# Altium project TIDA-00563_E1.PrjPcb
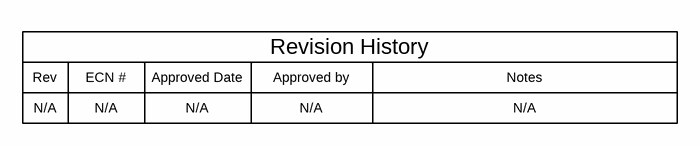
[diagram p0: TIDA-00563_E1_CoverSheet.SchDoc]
CopyrightYear: 2015; EVM_Orderable: N/A; PCB_Layout: SY; PCB_Rev: E1; PRJ_Customer: Public Release; PRJ_Engineer: FA&C; PRJ_Number: TIDA-00563; PRJ_Title: Inductive Proximity Switch BoosterPack; SCH_Rev: E1; TechSupport: http://www.ti.com/support; TID: TIDA-00563
3 sheets, 82 parts. Net scope: global (net labels, ports and power ports of the same name join across sheets).
Board file: TIDA-00563_E1.PcbDoc
Sheets:
  TIDA-00563_E1_CoverSheet.SchDoc
  TIDA-00563_E1_Hardware.SchDoc
  TIDA-00563_E1_LDC1101_BoosterPack.SchDoc

## Sheet TIDA-00563_E1_CoverSheet.SchDoc: Block Diagram
size 431 x 279 mm; Date: Not shown in title block; ApprovedBy: Not shown in title block; CheckedBy: Not shown in title block; Author: Not shown in title block; CompanyName: Not shown in title block; DrawnBy: SY; Engineer: Not shown in title block; Organization: Not shown in title block; Address1: Not shown in title block; Address2: Not shown in title block; Address3: Not shown in title block; Address4: Not shown in title block; DocumentNumber: 1; Revision: Use project parameter SCH_Rev; SheetNumber: 1; SheetTotal: 3; PageSetup: Record=PageOptions¦CenterHorizontal=True¦CenterVertical=True¦PrintScale=1.00¦XCorrection=1.00¦YCorrection=1.00¦PrintKind=0¦BorderSize=5000000¦LeftOffset=0¦BottomOffset=0¦Orientation=2¦PaperLength=1000¦PaperWidth=1000¦Scale=100¦PaperSource=15¦PrintQuality=600¦MediaType=1¦DitherType=10¦PaperKind=Letter¦PrintScaleMode=1

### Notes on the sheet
- Rev
- N/A
- ECN #
- Approved Date
- Approved by
- Revision History
- Notes

## Sheet TIDA-00563_E1_Hardware.SchDoc: Hardware
size 431 x 279 mm; Date: Not shown in title block; ApprovedBy: Not shown in title block; CheckedBy: Not shown in title block; Author: Not shown in title block; CompanyName: Not shown in title block; DrawnBy: SY; Engineer: Not shown in title block; Organization: Not shown in title block; Address1: Not shown in title block; Address2: Not shown in title block; Address3: Not shown in title block; Address4: Not shown in title block; DocumentNumber: 1; Revision: Use project parameter SCH_Rev; SheetNumber: 3; SheetTotal: 3; PageSetup: Record=PageOptions¦CenterHorizontal=True¦CenterVertical=True¦PrintScale=1.00¦XCorrection=1.00¦YCorrection=1.00¦PrintKind=0¦BorderSize=5000000¦LeftOffset=0¦BottomOffset=0¦Orientation=2¦PaperLength=1000¦PaperWidth=1000¦Scale=100¦PaperSource=15¦PrintQuality=600¦MediaType=1¦DitherType=10¦PaperKind=Letter¦PrintScaleMode=1
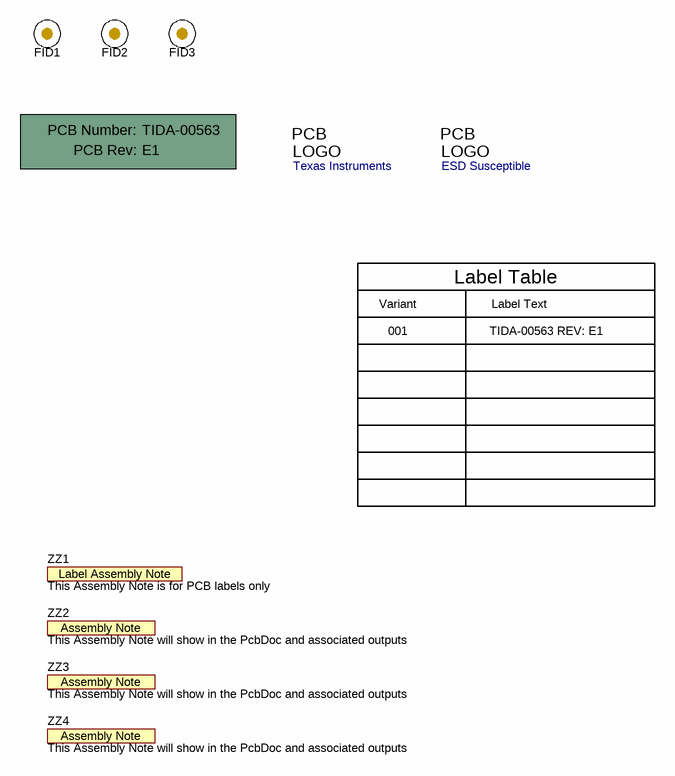
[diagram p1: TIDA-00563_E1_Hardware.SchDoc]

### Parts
!PCB1  Printed Circuit Board  (value not drawn)  (mechanical)
FID1  Fiducial  [Fiducial10-20]  (value not drawn)
FID2  Fiducial  [Fiducial10-20]  (value not drawn)
FID3  Fiducial  [Fiducial10-20]  (value not drawn)
Logo1  Texas Instruments  [TI_Stacked_Overlay_Medium_Vertical]  (no BOM)
Logo2  ESD Susceptible  [ESD_Overlay_Large]  (no BOM)
ZZ1  This Assembly Note is for PCB labels only  [AssemblyNoteLabel]  (no BOM)
ZZ2  This Assembly Note will show in the PcbDoc and associated outputs  [AssemblyNote]  (no BOM)
ZZ3  This Assembly Note will show in the PcbDoc and associated outputs  [AssemblyNote]  (no BOM)
ZZ4  This Assembly Note will show in the PcbDoc and associated outputs  [AssemblyNote]  (no BOM)

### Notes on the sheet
- Label Table
- Variant
- 001
- Label Text
- TIDA-00563 REV: E1

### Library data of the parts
!PCB1 = PCB: Manufacturer: Any; PartNumber: TIDA-00563; SymbolCreator: a0412235
FID1-FID3 = Fiducial: Fiducial mark.  There is nothing to buy or mount.; SymbolCreator: codlsc
Logo1 = TI_Logo: Texas Instrument Corporate Signature; SymbolCreator: a0412235
Logo2 = ESD_Susceptible: ESD Susceptible Symbol; SymbolCreator: a0412235
ZZ1 = AssemblyNoteLabel: SymbolCreator: a0412235
ZZ2-ZZ4 = AssemblyNote: SymbolCreator: codlsc

## Sheet TIDA-00563_E1_LDC1101_BoosterPack.SchDoc: MSP430 MCU & LDC1101 Interface Circuitry
size 431 x 279 mm; Date: Not shown in title block; ApprovedBy: Not shown in title block; CheckedBy: Not shown in title block; Author: Not shown in title block; CompanyName: Not shown in title block; DrawnBy: SY; Engineer: Not shown in title block; Organization: Not shown in title block; Address1: Not shown in title block; Address2: Not shown in title block; Address3: Not shown in title block; Address4: Not shown in title block; DocumentNumber: 1; Revision: Use project parameter SCH_Rev; SheetNumber: 2; SheetTotal: 3; PageSetup: Record=PageOptions¦CenterHorizontal=True¦CenterVertical=True¦PrintScale=1.00¦XCorrection=1.00¦YCorrection=1.00¦PrintKind=0¦BorderSize=5000000¦LeftOffset=0¦BottomOffset=0¦Orientation=2¦PaperLength=1000¦PaperWidth=1000¦Scale=100¦PaperSource=15¦PrintQuality=600¦MediaType=1¦DitherType=10¦PaperKind=Letter¦PrintScaleMode=1
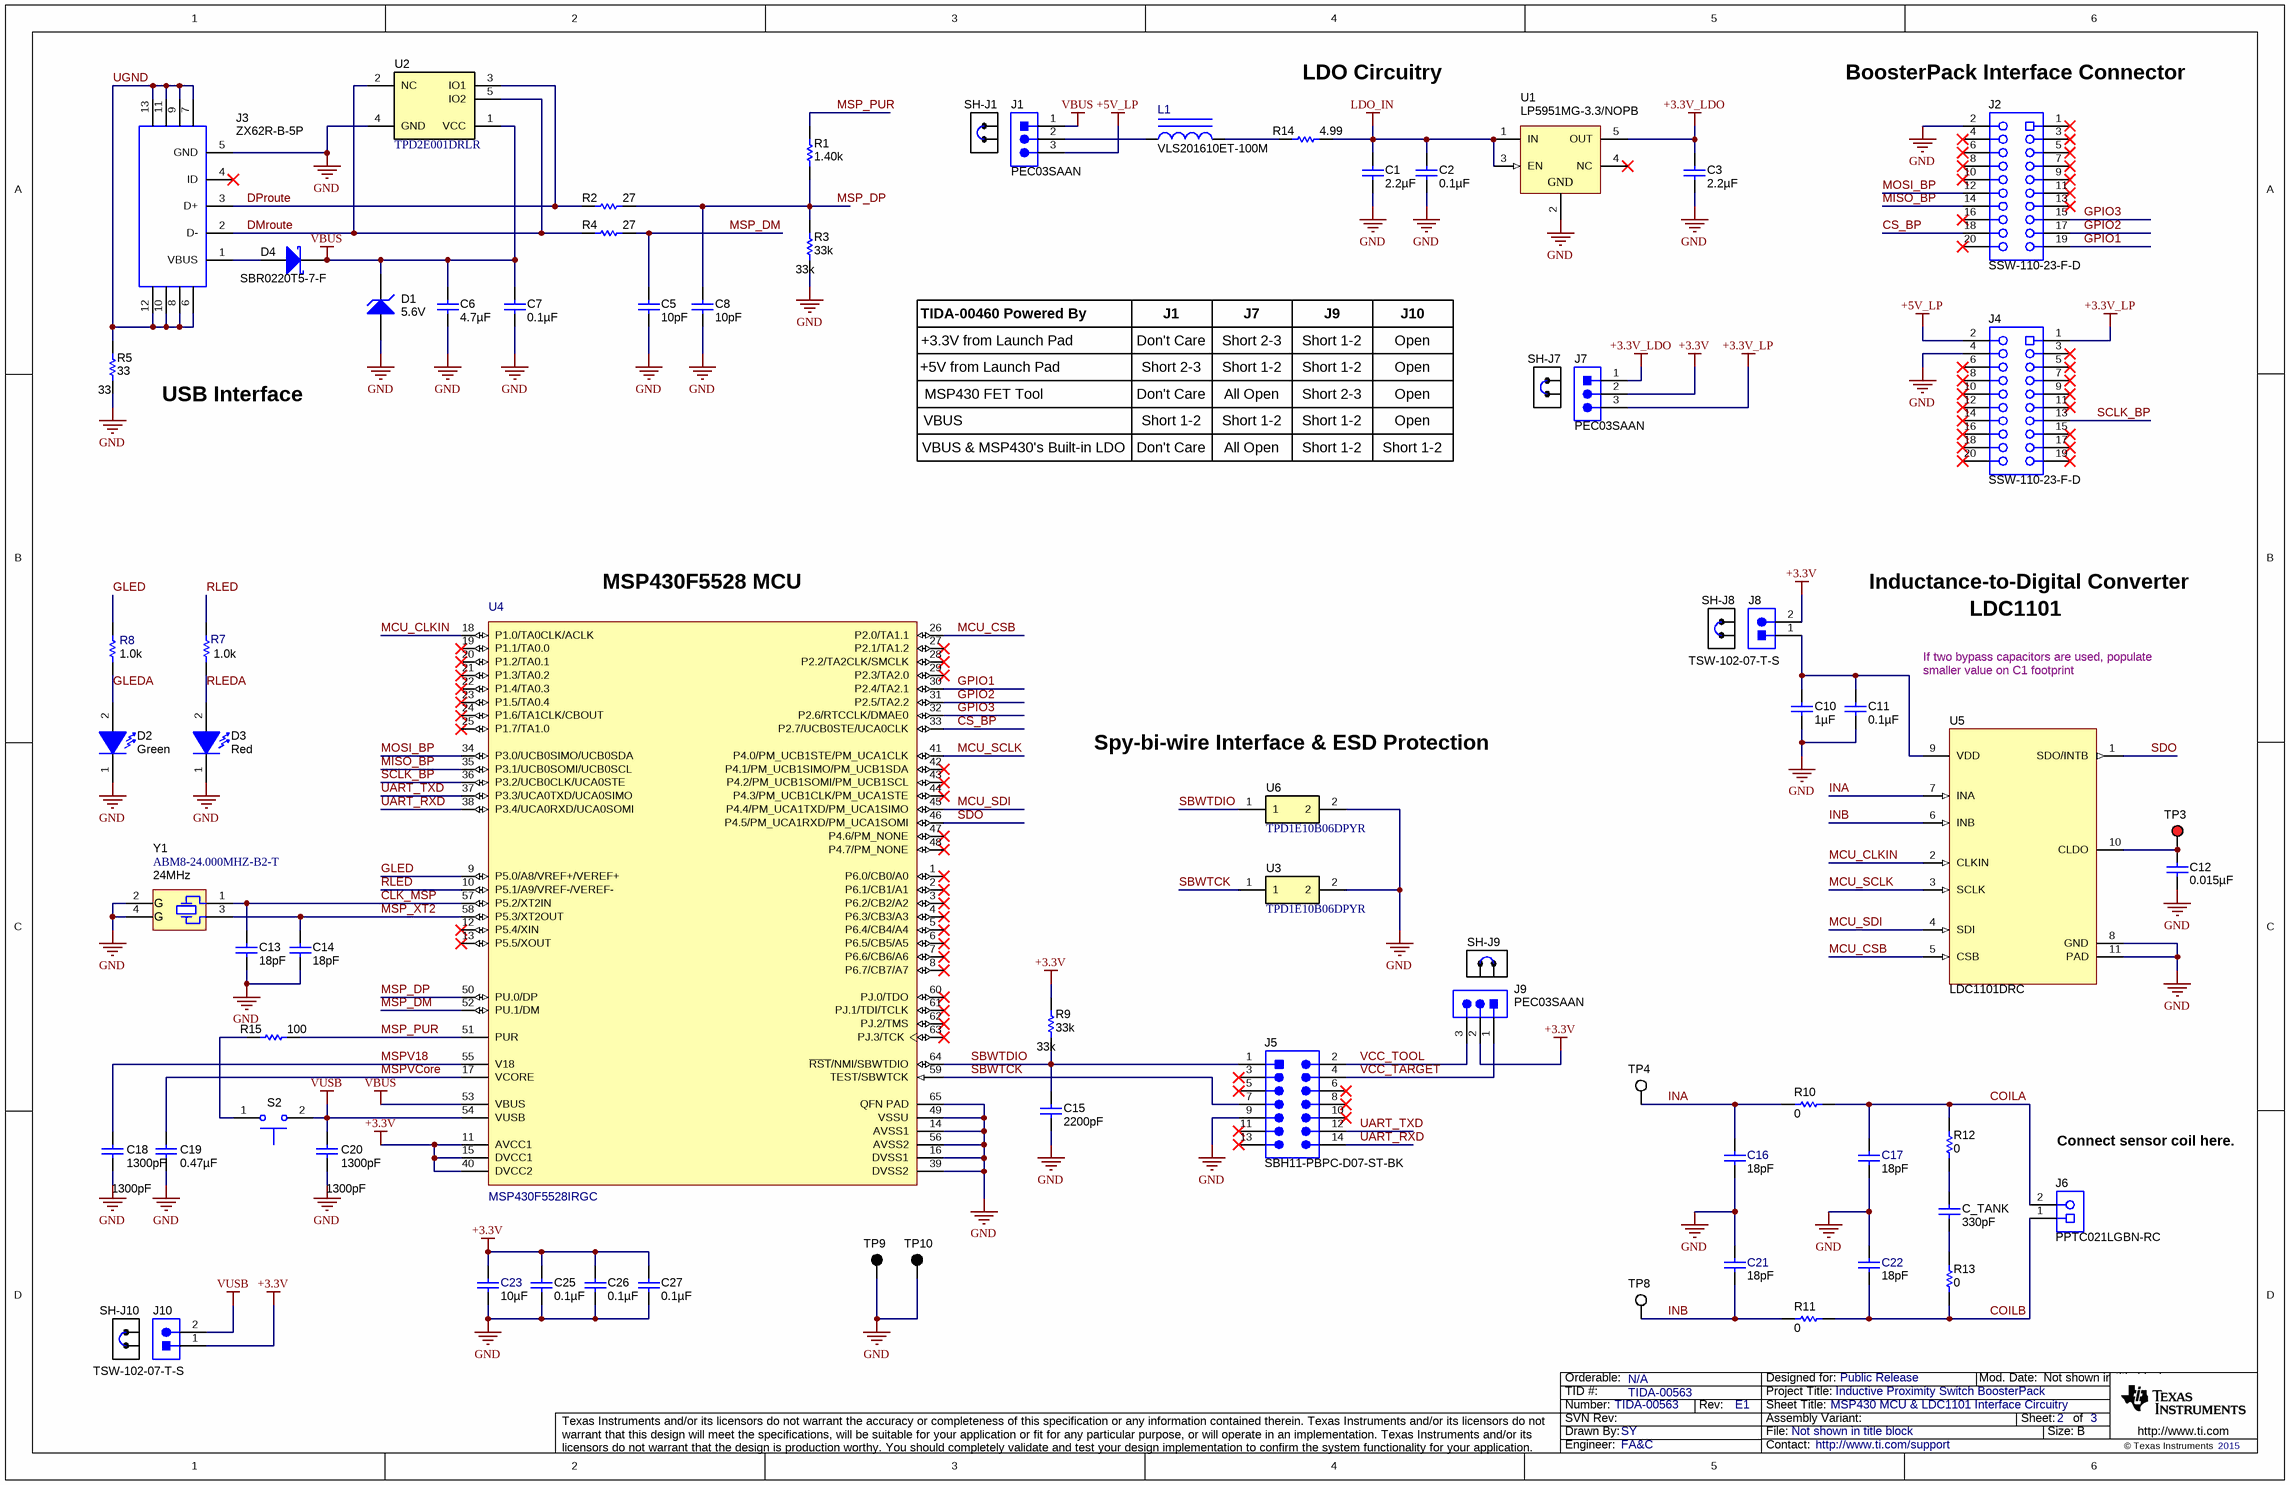
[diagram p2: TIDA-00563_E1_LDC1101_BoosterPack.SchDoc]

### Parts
C1  ValueDisplayed: 2.2µF  [0603]  (hidden comment: C0603C225K8PACTU)
C2  ValueDisplayed: 0.1µF  [0402]  (hidden comment: C1005X7R1H104K050BB)
C3  ValueDisplayed: 2.2µF  [0603]  (hidden comment: C0603C225K8PACTU)
C5  ValueDisplayed: 10pF  [0402]  (hidden comment: 500R07S100JV4T)
C6  ValueDisplayed: 4.7µF  [0805]  (hidden comment: GRM21BR71C475KA73L)
C7  ValueDisplayed: 0.1µF  [0402]  (hidden comment: C1005X7R1H104K050BB)
C8  ValueDisplayed: 10pF  [0402]  (hidden comment: 500R07S100JV4T)
C10  ValueDisplayed: 1µF  [0402]  (hidden comment: GRM155R61A105KE15D)
C11  ValueDisplayed: 0.1µF  [0402]  (hidden comment: C1005X7R1H104K050BB)
C12  ValueDisplayed: 0.015µF  [0603]  (hidden comment: GRM188R71C153KA01D)
C13  ValueDisplayed: 18pF  [0402]  (hidden comment: GRM1555C1H180JA01D)
C14  ValueDisplayed: 18pF  [0402]  (hidden comment: GRM1555C1H180JA01D)
C15  ValueDisplayed: 2200pF  [0402]  (hidden comment: GRM155R70J222KA01D)
C16  ValueDisplayed: 18pF  [0603]  (hidden comment: GRM1885C2A180JA01D)
C17  ValueDisplayed: 18pF  [0603]  (hidden comment: GRM1885C2A180JA01D)
C18  value 1300pF  [0402]  (hidden comment: 0402YC132KAT2A)
C19  ValueDisplayed: 0.47µF  [0603]  (hidden comment: C0603C474K8RACTU)
C20  value 1300pF  [0402]  (hidden comment: 0402YC132KAT2A)
C21  ValueDisplayed: 18pF  [0603]  (hidden comment: GRM1885C2A180JA01D)
C22  ValueDisplayed: 18pF  [0603]  (hidden comment: GRM1885C2A180JA01D)
C23  ValueDisplayed: 10µF  [0603]  (hidden comment: C1608X5R1A106M)
C25  ValueDisplayed: 0.1µF  [0402]  (hidden comment: C1005X7R1H104K050BB)
C26  ValueDisplayed: 0.1µF  [0402]  (hidden comment: C1005X7R1H104K050BB)
C27  ValueDisplayed: 0.1µF  [0402]  (hidden comment: C1005X7R1H104K050BB)
C_TANK  ValueDisplayed: 330pF  [0603]  (hidden comment: C1608C0G1H331F080AA)
D1  value 5.6V  [SOD-123]  (hidden comment: MMSZ5232B-7-F)
D2  value Green  [WL-SMCW_GREEN]  (hidden comment: 150060GS75000)
D3  value Red  [WL-SMCW_RED]  (hidden comment: 150060RS75000)
D4  SBR0220T5-7-F  [SOD-523]
J1  PEC03SAAN  [CONN_PEC03SAAN]
J2  SSW-110-23-F-D  [CONN_SSW-110-23-F-D]
J3  ZX62R-B-5P  [Hirose_ZX62R-B-5P]
J4  SSW-110-23-F-D  [CONN_SSW-110-23-F-D]
J5  SBH11-PBPC-D07-ST-BK  [CONN_SBH11-PBPC-D07-ST-BK]
J6  PPTC021LGBN-RC  [Sullins_xPxC021LGBN]
J7  PEC03SAAN  [CONN_PEC03SAAN]
J8  TSW-102-07-T-S  [Samtec_TSW-102-07-T-S]
J9  PEC03SAAN  [CONN_PEC03SAAN]
J10  TSW-102-07-T-S  [Samtec_TSW-102-07-T-S]
L1  VLS201610ET-100M  [VLS201610ET]
R1  ValueDisplayed: 1.40k  [0402]  (hidden comment: ERJ-2RKF1401X)
R2  ValueDisplayed: 27  [0402]  (hidden comment: CRCW040227R0JNED)
R3  value 33k  [0402]  (hidden comment: CRCW040233K0JNED)
R4  ValueDisplayed: 27  [0402]  (hidden comment: CRCW040227R0JNED)
R5  value 33  [0603]  (hidden comment: CRCW060333R0JNEA)
R7  value 1.0k  [0402]  (hidden comment: CRCW04021K00JNED)
R8  value 1.0k  [0402]  (hidden comment: CRCW04021K00JNED)
R9  value 33k  [0402]  (hidden comment: CRCW040233K0JNED)
R10  ValueDisplayed: 0  [0603]  (hidden comment: ERJ-3GEY0R00V)
R11  ValueDisplayed: 0  [0603]  (hidden comment: ERJ-3GEY0R00V)
R12  ValueDisplayed: 0  [0402]  (hidden comment: CRCW04020000Z0ED)
R13  ValueDisplayed: 0  [0402]  (hidden comment: CRCW04020000Z0ED)
R14  ValueDisplayed: 4.99  [0603]  (hidden comment: RC0603FR-074R99L)
R15  ValueDisplayed: 100  [0402]  (hidden comment: ERJ-2RKF1000X)
S2  SKRKAEE010  [SW_SKRKAEE010]  (value not drawn)
SH-J1  969102-0000-DA  [SNT-100-BK-G]  (value not drawn)
SH-J7  969102-0000-DA  [SNT-100-BK-G]  (value not drawn)
SH-J8  969102-0000-DA  [SNT-100-BK-G]  (value not drawn)
SH-J9  969102-0000-DA  [SNT-100-BK-G]  (value not drawn)
SH-J10  969102-0000-DA  [SNT-100-BK-G]  (value not drawn)
TP3  5000  [Keystone5000]  (value not drawn)
TP4  5002  [Keystone5002]  (value not drawn)
TP8  5002  [Keystone5002]  (value not drawn)
TP9  5001  [Keystone5001]  (value not drawn)
TP10  5001  [Keystone5001]  (value not drawn)
U1  LP5951MG-3.3/NOPB  [MAA05A_N]
U2  TPD2E001DRLR  [DRL0005A]
U3  TPD1E10B06DPYR  [DPY0002A]
U4  MSP430F5528IRGC  [RGC0064B]
U5  LDC1101DRC  [DRC0010J]
U6  TPD1E10B06DPYR  [DPY0002A]
Y1  ABM8-24.000MHZ-B2-T  Frequency: 24MHz  [XTAL_ABM8]

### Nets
+3.3V: C23.1 C25.1 C26.1 C27.1 J7.2 J8.2 J9.2 J10.1 R9.1 U4.11(AVCC1) U4.15(DVCC1) U4.40(DVCC2)
+3.3V_LDO: C3.1 J7.1 U1.5(OUT)
+3.3V_LP: J4.1 J7.3
+5V_LP: J1.3 J4.2
GND: C1.2 C2.2 C3.2 C5.2 C6.2 C7.2 C8.2 C10.2 C11.2 C12.2 C13.2 C14.2 C15.2 C16.1 C17.1 C18.2 C19.2 C20.2 C21.2 C22.2 C23.2 C25.2 C26.2 C27.2 D1.2(A) D2.1(K) D3.1(K) J2.2 J3.5(GND) J4.4 J5.9 R3.1 R5.1 TP9.1 TP10.1 U1.2(GND) U2.4(GND) U3.2 U4.14(AVSS1) U4.16(DVSS1) U4.39(DVSS2) U4.49(VSSU) U4.56(AVSS2) U4.65(QFN_PAD) U5.8(GND) U5.11(PAD) U6.2 Y1.2(GND) Y1.4(GND)
LDO_IN: C1.1 C2.1 R14.2 U1.1(IN) U1.3(EN)
VBUS: C6.1 C7.1 D1.1(K) D4.1(K) J1.1 U2.1(VCC) U4.53(VBUS)
VUSB: C20.1 J10.2 S2.2 U4.54(VUSB)
CLK_MSP: C13.1 U4.57(P5.2/XT2IN) Y1.1
COILA: C17.2 J6.2 R10.2 R12.2
COILB: C22.1 J6.1 R11.2 R13.1
CS_BP: J2.18 U4.33(P2.7/UCB0STE/UCA0CLK)
DMroute: J3.2(D-) R4.1 U2.2(NC) U2.5(IO2)
DProute: J3.3(D+) R2.1 U2.3(IO1)
GLED: R8.1 U4.9(P5.0/A8/VREF+/VEREF+)
GLEDA: D2.2(A) R8.2
GPIO1: J2.19 U4.30(P2.4/TA2.1)
GPIO2: J2.17 U4.31(P2.5/TA2.2)
GPIO3: J2.15 U4.32(P2.6/RTCCLK/DMAE0)
INA: C16.2 R10.1 TP4.1 U5.7(INA)
INB: C21.1 R11.1 TP8.1 U5.6(INB)
MCU_CLKIN: U4.18(P1.0/TA0CLK/ACLK) U5.2(CLKIN)
MCU_CSB: U4.26(P2.0/TA1.1) U5.5(CSB)
MCU_SCLK: U4.41(P4.0/PM_UCB1STE/PM_UCA1CLK) U5.3(SCLK)
MCU_SDI: U4.45(P4.4/PM_UCA1TXD/PM_UCA1SIMO) U5.4(SDI)
MISO_BP: J2.14 U4.35(P3.1/UCB0SOMI/UCB0SCL)
MOSI_BP: J2.12 U4.34(P3.0/UCB0SIMO/UCB0SDA)
MSP_DM: C5.1 R4.2 U4.52(PU.1/DM)
MSP_DP: C8.1 R1.1 R2.2 R3.2 U4.50(PU.0/DP)
MSP_PUR: R1.2 R15.1 U4.51(PUR)
MSP_XT2: C14.1 U4.58(P5.3/XT2OUT) Y1.3
MSPV18: C18.1 U4.55(V18)
MSPVCore: C19.1 U4.17(VCORE)
RLED: R7.1 U4.10(P5.1/A9/VREF-/VEREF-)
RLEDA: D3.2(A) R7.2
SBWTCK: J5.7 U3.1 U4.59(TEST/SBWTCK)
SBWTDIO: C15.1 J5.1 R9.2 U4.64(~{RST}/NMI/SBWTDIO) U6.1
SCLK_BP: J4.13 U4.36(P3.2/UCB0CLK/UCA0STE)
SDO: U4.46(P4.5/PM_UCA1RXD/PM_UCA1SOMI) U5.1(SDO/INTB)
UART_RXD: J5.14 U4.38(P3.4/UCA0RXD/UCA0SOMI)
UART_TXD: J5.12 U4.37(P3.3/UCA0TXD/UCA0SIMO)
UGND: J3.6 J3.7 J3.8 J3.9 J3.10 J3.11 J3.12 J3.13 R5.2
VCC_TARGET: J5.4 J9.1
VCC_TOOL: J5.2 J9.3
NetC10_1: C10.1 C11.1 J8.1 U5.9(VDD)
NetC12_1: C12.1 TP3.1 U5.10(CLDO)
NetC_TANK_1: C_TANK.1 R12.1
NetC_TANK_2: C_TANK.2 R13.2
NetD4_2: D4.2(A) J3.1(VBUS)
NetJ1_2: J1.2 L1.1
NetL1_2: L1.2 R14.1
NetR15_2: R15.2 S2.1

Not connected (* = marked no-connect by the designer): J2 1* 3* 4* 5* 6* 7* 8* 9* 10* 11* 13* 16* 20*; J3 4(ID)*; J4 3* 5* 6* 7* 8* 9* 10* 11* 12* 14* 15* 16* 17* 18* 19* 20*; J5 3* 5* 6* 8* 10* 11* 13*; U1 4(NC)*; U4 1(P6.0/CB0/A0)* 2(P6.1/CB1/A1)* 3(P6.2/CB2/A2)* 4(P6.3/CB3/A3)* 5(P6.4/CB4/A4)* 6(P6.5/CB5/A5)* 7(P6.6/CB6/A6)* 8(P6.7/CB7/A7)* 12(P5.4/XIN)* 13(P5.5/XOUT)* 19(P1.1/TA0.0)* 20(P1.2/TA0.1)* 21(P1.3/TA0.2)* 22(P1.4/TA0.3)* 23(P1.5/TA0.4)* 24(P1.6/TA1CLK/CBOUT)* 25(P1.7/TA1.0)* 27(P2.1/TA1.2)* 28(P2.2/TA2CLK/SMCLK)* 29(P2.3/TA2.0)* 42(P4.1/PM_UCB1SIMO/PM_UCB1SDA)* 43(P4.2/PM_UCB1SOMI/PM_UCB1SCL)* 44(P4.3/PM_UCB1CLK/PM_UCA1STE)* 47(P4.6/PM_NONE)* 48(P4.7/PM_NONE)* 60(PJ.0/TDO)* 61(PJ.1/TDI/TCLK)* 62(PJ.2/TMS)* 63(PJ.3/TCK)*

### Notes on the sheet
- LDO Circuitry
- (near J2) BoosterPack Interface Connector
- +5V from Launch Pad
- +3.3V from Launch Pad
- TIDA-00460 Powered By
- J1
- Don't Care
- Short 2-3
- J7
- Short 1-2
- J9
- J10
- Open
- (near R5) USB Interface
- VBUS
- MSP430 FET Tool
- All Open
- VBUS & MSP430's Built-in LDO
- (near U4) MSP430F5528 MCU
- LDC1101
- Inductance-to-Digital Converter
- If two bypass capacitors are used, populate smaller value on C1 footprint
- Spy-bi-wire Interface & ESD Protection
- (near J6) Connect sensor coil here.

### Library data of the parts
C1 C3 = C0603C225K8PACTU: CAP, CERM, 2.2 µF, 10 V, +/- 10%, X5R, 0603; Manufacturer: Kemet; Polarized: N; CompType: Capacitor; Value: 2.2uF; U/M: EA; Cap_F: 0.0000022; Tolerance_%: 10; Value1: Unknown; Value2: 10V; TaMin_C: -55; TaMax_C: 85; AEC Category: Q200
C2 C7 C11 C25-C27 = C1005X7R1H104K050BB: CAP, CERM, 0.1 µF, 50 V, +/- 10%, X7R, 0402; Manufacturer: TDK; Polarized: N; CompType: Capacitor; Value: 0.1uF; U/M: EA; Cap_F: 0.0000001; Tolerance_%: 10; Value1: Unknown; VDC_V: 50; Value2: 50V; TaMin_C: -55; TaMax_C: 125; AEC Category: Q200
C5 C8 = 500R07S100JV4T: CAP, CERM, 10 pF, 50 V, +/- 5%, C0G/NP0, 0402; Manufacturer: Johanson Technology; Polarized: N; CompType: Capacitor; Value: 10pF; U/M: EA; Cap_F: 0.00000000001; Tolerance_%: 5; Value1: Unknown; VDC_V: 50; Value2: 50V; TaMin_C: -55; TaMax_C: 125; AEC Category: Q200
C6 = GRM21BR71C475KA73L: CAP, CERM, 4.7 µF, 16 V, +/- 10%, X7R, 0805; Manufacturer: MuRata; Polarized: N; CompType: Capacitor; Value: 4.7uF; U/M: EA; Cap_F: 0.0000047; Tolerance_%: 10; ESR_ohm: 0.006; Value1: 0.006 ohm; VDC_V: 16; Value2: 16V; TaMin_C: -55; TaMax_C: 125; AEC Category: Q200
C10 = GRM155R61A105KE15D: CAP, CERM, 1 µF, 10 V, +/- 10%, X5R, 0402; Manufacturer: MuRata; Polarized: N; CompType: Capacitor; Value: 1uF; U/M: EA; Cap_F: 0.000001; Tolerance_%: 10; Value1: Unknown; Value2: 10V; TaMin_C: -55; TaMax_C: 85; AEC Category: Q200
C12 = GRM188R71C153KA01D: CAP, CERM, 0.015 µF, 16 V, +/- 10%, X7R, 0603; Manufacturer: MuRata; Polarized: N; CompType: Capacitor; Value: 0.015uF; U/M: EA; Cap_F: 0.000000015; Tolerance_%: 10; Value1: Unknown; VDC_V: 16; Value2: 16V; TaMin_C: -55; TaMax_C: 125; AEC Category: Q200
C13 C14 = GRM1555C1H180JA01D: CAP, CERM, 18 pF, 50 V, +/- 5%, C0G/NP0, 0402; Manufacturer: MuRata; Polarized: N; CompType: Capacitor; Value: 18pF; U/M: EA; Cap_F: 0.000000000018; Tolerance_%: 5; Value1: Unknown; VDC_V: 50; Value2: 50V; TaMin_C: -55; TaMax_C: 125; AEC Category: Q200
C15 = GRM155R70J222KA01D: CAP, CERM, 2200 pF, 6.3 V, +/- 10%, X7R, 0402; Manufacturer: MuRata; Polarized: N; CompType: Capacitor; Value: 2200pF; U/M: EA; Cap_F: 0.0000000022; Tolerance_%: 10; Value1: Unknown; VDC_V: 6.3; Value2: 6.3V; TaMin_C: -55; TaMax_C: 125; AEC Category: Q200
C16 C17 C21 C22 = GRM1885C2A180JA01D: CAP, CERM, 18 pF, 100 V, +/- 5%, C0G/NP0, 0603; Manufacturer: MuRata; Polarized: N; CompType: Capacitor; Value: 18pF; U/M: EA; Cap_F: 0.000000000018; Tolerance_%: 5; Value1: Unknown; VDC_V: 100; Value2: 100V; TaMin_C: -55; TaMax_C: 125; AEC Category: Q200
C18 C20 = 0402YC132KAT2A: CAP, CERM, 1300 pF, 16 V, +/- 10%, X7R, 0402; Manufacturer: AVX; Polarized: N; CompType: Capacitor; U/M: EA; Cap_F: 0.0000000013; Tolerance_%: 10; VDC_V: 16; TaMin_C: -55; TaMax_C: 125; Value1: Unknown; Value2: 16V; AEC Category: Q200
C19 = C0603C474K8RACTU: CAP, CERM, 0.47 µF, 10 V, +/- 10%, X7R, 0603; Manufacturer: Kemet; Polarized: N; CompType: Capacitor; Value: 0.47uF; U/M: EA; Cap_F: 0.00000047; Tolerance_%: 10; Value1: Unknown; Value2: 10V; TaMin_C: -55; TaMax_C: 125; AEC Category: Q200
C23 = C1608X5R1A106M: CAP, CERM, 10 µF, 10 V, +/- 20%, X5R, 0603; Manufacturer: TDK; Polarized: N; CompType: Capacitor; Value: 10uF; U/M: EA; Cap_F: 0.00001; Tolerance_%: 20; ESR_ohm: 0.0078; Value1: 0.0078 ohm; VDC_V: 10; Value2: 10V; IRMS_A: 1.85; TaMin_C: -55; TaMax_C: 85; AEC Category: Q200
C_TANK = C1608C0G1H331F080AA: CAP, CERM, 330 pF, 50 V, +/- 1%, C0G/NP0, 0603; Manufacturer: TDK; Polarized: N; CompType: Capacitor; Value: 330pF; U/M: EA; Cap_F: 0.00000000033; Tolerance_%: 1; Value1: Unknown; VDC_V: 50; Value2: 50V; TaMin_C: -55; TaMax_C: 125; AEC Category: Q200
D1 = MMSZ5232B-7-F: Diode, Zener, 5.6 V, 500 mW, SOD-123; Manufacturer: Diodes Inc.; U/M: EA; Power_W: 0.5; Vz_V: 5.6; Value1: 0.5W; RJA_CperW: 350; SymbolCreator: a0412235; AEC Category: Q101
D2 = 150060GS75000: LED, Green, SMD; Manufacturer: Wurth Elektronik; Type: InGaN; Vf_V: 3.2; Value2: 3.2V; Io_A: 0.02; Tjmax_C: 85; Value1: W; Angle: 140; U/M: EA
D3 = 150060RS75000: LED, Red, SMD; Manufacturer: Wurth Elektronik; Type: AlInGaP; Vf_V: 2; Value2: 2V; Io_A: 0.03; Vr_V: 5; Tjmax_C: 85; Power_TotalModule: 0.072; Value1: 0.072W; Angle: 140; U/M: EA
D4 = SBR0220T5-7-F: Diode, Schottky, 20 V, 0.2 A, SOD-523; Manufacturer: Diodes Inc.; U/M: EA; Vf_V: 0.47; Value: 20V; Value1: 0.2A; Value2: 0.47V; Io_A: 0.2; Vr_V: 20; AEC Category: Q101
J1 J7 J9 = PEC03SAAN: Header, 100mil, 3x1, Tin plated, TH; Manufacturer: Sullins Connector Solutions; SymbolCreator: a0799628; U/M: EA
J2 J4 = SSW-110-23-F-D: Connector, Receptacle, 100mil, 10x2, Gold plated, TH; Manufacturer: Samtec; SymbolCreator: a0412235; U/M: EA
J3 = ZX62R-B-5P: Connector, Receptacle, Micro-USB Type B, SMT; Manufacturer: Hirose Electric Co. Ltd.; SymbolCreator: a0799628; U/M: EA
J5 = SBH11-PBPC-D07-ST-BK: Header (shrouded), 100 mil, 7x2, Gold plated, TH; Manufacturer: Sullins Connector Solutions; SymbolCreator: a0412235; CompType: Connector; U/M: EA
J6 = PPTC021LGBN-RC: Receptacle, 2.54 mm, 2x1, Tin, R/A, SMT; Manufacturer: Sullins Connector Solutions; SymbolCreator: a0412235; U/M: EA
J8 J10 = TSW-102-07-T-S: Header, 2.54 mm, 2x1, Tin, TH; Manufacturer: Samtec; SymbolCreator: a0412235; U/M: EA
L1 = VLS201610ET-100M: Inductor, Shielded, Ferrite, 10 µH, 0.4 A, 1.38 ohm, SMD; Manufacturer: TDK; Value: 10uH; Ind_H: 10.0E-6; ValueDisplayed: 10µH; Imax_A: 0.4; Irms: 0.42A @ 40C rise; Isat: 0.4A @ 30% inductance drop; DCR_ohm: 1.38; Value2: 0.4A; AEC Category: Q200
R1 = ERJ-2RKF1401X: RES, 1.40 k, 1%, 0.1 W, 0402; Manufacturer: Panasonic; CompType: Resistor; Value: 1.40k; Res_ohm: 1400; Value_Code: 1k40; Tolerance_%: 1; Power_W: 0.1; Value2: 0.1W; VDC_V: 50; TempCo: 100 ppm/C; EIA_Code: E96; U/M: EA; AEC Category: Q200
R2 R4 = CRCW040227R0JNED: RES, 27, 5%, 0.063 W, 0402; Manufacturer: Vishay-Dale; CompType: Resistor; Value: 27; Value_Code: 27R0; Tolerance_%: 5; Power_W: 0.063; Value2: 0.063W; VDC_V: 50; TempCo: 200 ppm/C; EIA_Code: E24; U/M: EA; AEC Category: Q200
R3 R9 = CRCW040233K0JNED: RES, 33 k, 5%, 0.063 W, 0402; Manufacturer: Vishay-Dale; CompType: Resistor; Res_ohm: 33000; Value_Code: 33k0; Tolerance_%: 5; Power_W: 0.063; Value2: 0.063W; VDC_V: 50; TempCo: 200 ppm/C; EIA_Code: E24; U/M: EA; AEC Category: Q200
R5 = CRCW060333R0JNEA: RES, 33, 5%, 0.1 W, 0603; Manufacturer: Vishay-Dale; CompType: Resistor; Value_Code: 33R0; Tolerance_%: 5; Power_W: 0.1; Value2: 0.1W; VDC_V: 75; TempCo: 200 ppm/C; EIA_Code: E24; U/M: EA; AEC Category: Q200
R7 R8 = CRCW04021K00JNED: RES, 1.0 k, 5%, 0.063 W, 0402; Manufacturer: Vishay-Dale; CompType: Resistor; Res_ohm: 1000; Value_Code: 1k00; Tolerance_%: 5; Power_W: 0.063; Value2: 0.063W; VDC_V: 50; TempCo: 200 ppm/C; EIA_Code: E24; U/M: EA; AEC Category: Q200
R10 R11 = ERJ-3GEY0R00V: RES, 0, 5%, 0.1 W, 0603; Manufacturer: Panasonic; CompType: Resistor; Value: 0; Value_Code: 0000; Tolerance_%: 5; Power_W: 0.1; Value2: 0.1W; VDC_V: 50; TempCo: 600 ppm/C; EIA_Code: E24; U/M: EA; AEC Category: Q200
R12 R13 = CRCW04020000Z0ED: RES, 0, 5%, 0.063 W, 0402; Manufacturer: Vishay-Dale; CompType: Resistor; Value: 0; Value_Code: 0000; Tolerance_%: 5; Power_W: 0.063; Value2: 0.063W; VDC_V: 50; TempCo: 200 ppm/C; EIA_Code: E24; U/M: EA; AEC Category: Q200
R14 = RC0603FR-074R99L: RES, 4.99, 1%, 0.1 W, 0603; Manufacturer: Yageo America; CompType: Resistor; Value: 4.99; Value_Code: 4R99; Tolerance_%: 1; Power_W: 0.1; Value2: 0.1W; VDC_V: 150; TempCo: 200 ppm/C; EIA_Code: E96; U/M: EA; AEC Category: Q200
R15 = ERJ-2RKF1000X: RES, 100, 1%, 0.1 W, 0402; Manufacturer: Panasonic; CompType: Resistor; Value: 100; Value_Code: 100R; Tolerance_%: 1; Power_W: 0.1; Value2: 0.1W; VDC_V: 50; TempCo: 100 ppm/C; EIA_Code: E96; U/M: EA; AEC Category: Q200
S2 = SKRKAEE010: Switch, Push Button, SMD; Manufacturer: Alps; SymbolCreator: a0412235; Circuit: SPST-NO; VDC_V: 12; SwitchFunction: Off-Mom; PositionCount: 1; CurrentRating_mA: 50
SH-J1 SH-J7-SH-J10 = 969102-0000-DA: Shunt, 100mil, Gold plated, Black; Manufacturer: 3M; Alternate Manufacturer: Samtec; Value: 1x2; Note: You can "mate" this to a header by matching the designator.  i.e. use SH-J3 for header J3
TP3 = 5000: Test Point, Miniature, Red, TH; Manufacturer: Keystone; CompType: Test Point Loop; U/M: EA
TP4 TP8 = 5002: Test Point, Miniature, White, TH; Manufacturer: Keystone; CompType: Test Point Loop; U/M: EA
TP9 TP10 = 5001: Test Point, Miniature, Black, TH; Manufacturer: Keystone; CompType: Test Point Loop; U/M: EA
U1 = LP5951MG-3.3/NOPB: Micropower, 150mA Low-Dropout CMOS Voltage Regulator, 5-pin SC-70, Pb-Free; Manufacturer: Texas Instruments; PackageTopMarking: LAB*XTT; PowerWise: N; CompType: LDO IC
U2 = TPD2E001DRLR: Low-Capacitance + / - 15 kV ESD-Protection Array for High-Speed Data Interfaces, 2 Channels, -40 to +85 degC, 5-pin SOT (DRL), Green (RoHS & no Sb/Br); Manufacturer: Texas Instruments; Alternate PartNumber: Equivalent; Breakdown Voltage(Min)(V): 11; IEC 61000-4-2 Air-Gap(+/- kV): 15; IEC 61000-4-2 Contact(+/- kV): 8; IO Capacitance(Typ)(pF): 1.5; IO Leakage Current(nA): 1; SubFamily: ESD Solution; USB High Speed: TRUE
U3 U6 = TPD1E10B06DPYR: ESD in 0402 Package with 10 pF Capacitance and 6 V Breakdown, 1 Channel, -40 to +125 degC, 2-pin X2SON (DPY), Green (RoHS & no Sb/Br); Manufacturer: Texas Instruments; Alternate PartNumber: Equivalent; Breakdown Voltage(Min)(V): 6; Eco-Plan: TBD; IEC 61000-4-2 Air-Gap(+/- kV): 30; IO Capacitance(Typ)(pF): 10; SubFamily: ESD Solution
U4 = MSP430F5528IRGC: Mixed Signal MicroController, RGC0064B; Manufacturer: Texas Instruments; Alternate Manufacturer: None; ADC: 12-bit SAR; ADC Channels: 16; Brown Out Reset: Yes; DMA: 3; Eco-Plan: Green (RoHS & no Sb/Br); Flash(KB): 128; Frequency(MHz): 25; GPIO: 47; Multiplier: 32x32; SRAM(B): 8192; SubFamily: 5 Series; Timers - 16-bit: 4; USB: 1; USCI_A (UART/LIN/IrDA/SPI): 2; SymbolCreator: Altium/a0412235; CompType: IC; U/M: EA
U5 = LDC1101DRC: 1.8V High Resolution Inductance to Digital Converter, DRC0010J; Alternate Manufacturer: None; Manufacturer: Texas Instruments; SymbolCreator: a0799628; CompType: IC; U/M: EA
Y1 = ABM8-24.000MHZ-B2-T: Crystal, 24.000MHz, 18pF, SMD; Manufacturer: Abracon Corportation; SymbolCreator: a0412235; U/M: EA; TaMin_C: -20; TaMax_C: 70; Frequency Stability: ±50ppm

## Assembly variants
001: not fitted FID1 FID2 FID3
